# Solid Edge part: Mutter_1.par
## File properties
Sűrűség: 0,000 kg/m^3
Pontosság: 0,990
Author: ahadarics
Last saved by: ahadarics
Revision: 76
Username: ahadarics
Dokumentum tartalom típus: 0
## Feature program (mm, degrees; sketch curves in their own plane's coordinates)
base feature "unnamed BaseFeature 1"
thread "unnamed Thread 1"
chamfer "Letörés_1"  SetBackValue2 = 60 deg
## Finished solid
Body 1: solid body, 23 faces, 46 edges, 24 vertices.
  Faces by surface: cone 14, plane 8, cylinder 1
  Edges by curve: spline 24, circle 16, line 6
Bounding box of the edges (mm): 6.000 x 19.630 x 17.000, from (0, -9.815, -8.5) to (6, 9.815, 8.5).
Cylindrical faces by radius (mm): R4.3235 x1
Conical faces (half-angle, radius in mm at the cone's reference point): 60 deg R4.3235 x1, 60 deg R5.0163 x1, 60 deg R9.1575 x12
Planar faces by outward normal: +x 1, +z 1, -x 1, -z 1, oblique 4
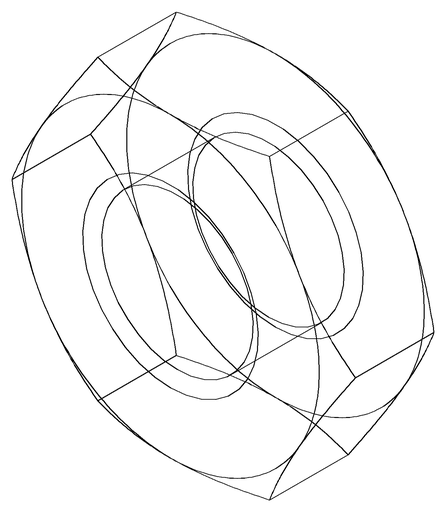
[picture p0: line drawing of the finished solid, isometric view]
